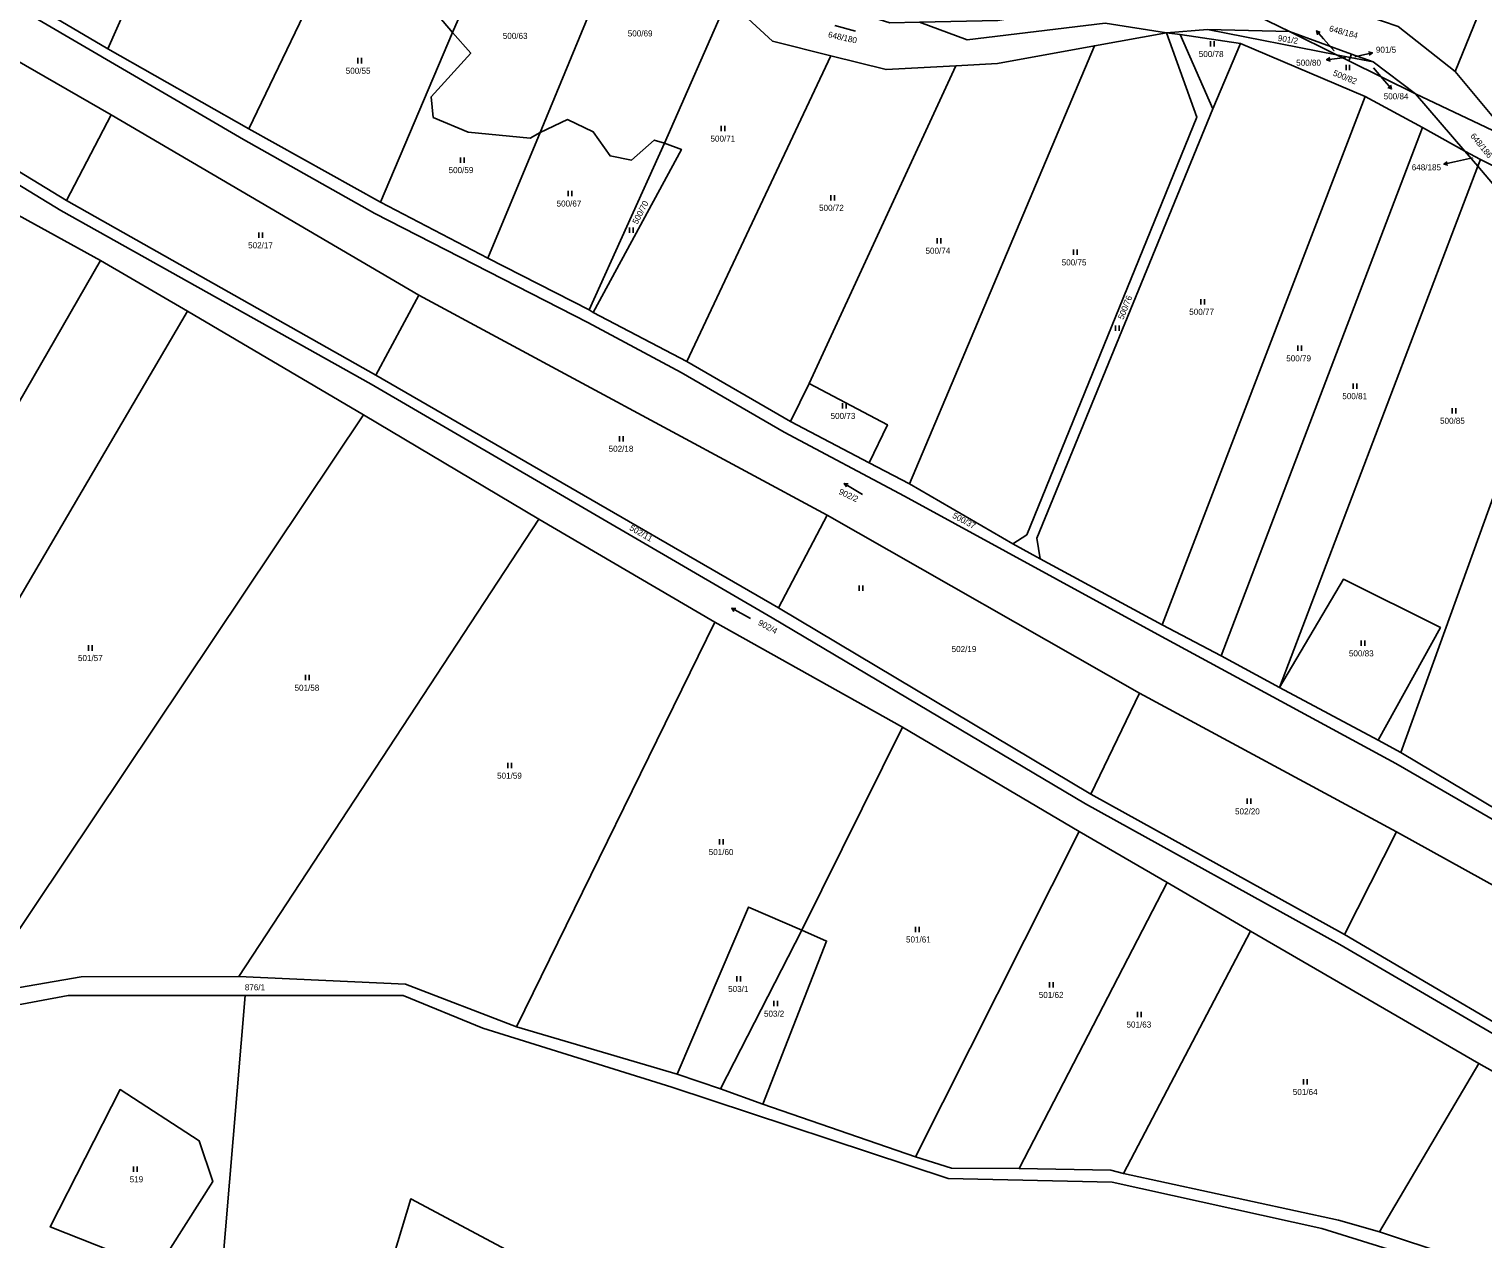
# Model space of a CAD drawing. Extents: x -654083 to -650132, y -1099819 to -1096699.
# Drawn here: x -651463.8 to -651055.5, y -1098945.7 to -1098606 of the extents above; entities that cross this region are included whole.
import ezdxf

# ---------------------------------------------------------------- set-up
doc = ezdxf.new("R2010")
doc.units = 0
for name, color, linetype in [('Obvody jako plochy', 7, 'Continuous'), ('Parcelní čísla', 7, 'Continuous'), ('Prvky pro prodl_ par_ č_', 7, 'Continuous'), ('Značky kultur', 7, 'Continuous')]:
    doc.layers.add(name, color=color, linetype=linetype)

msp = doc.modelspace()

# ---------------------------------------------------------------- linework, layer by layer
at = {"layer": 'Obvody jako plochy'}
for points in [[(-651063.28, -1098617.85), (-650992.27, -1098443.62), (-651020.25, -1098435.16), (-651088.04, -1098602.28), (-651079.27, -1098605.24)], [(-651003.38, -1098546.99), (-650965.66, -1098454.1), (-650992.27, -1098443.62), (-651063.28, -1098617.85), (-651047.34, -1098636.99), (-651041.11, -1098639.89)], [(-651454.84, -1098656.9), (-651367.65, -1098705.69), (-651255.05, -1098771.28), (-651167.08, -1098823.5), (-651095.7, -1098863.03), (-651026.53, -1098903.28), (-650920.69, -1098965.31), (-650919.42, -1098962.9), (-651025.16, -1098900.83), (-651094.31, -1098860.23), (-651165.63, -1098820.84), (-651253.31, -1098768.53), (-651366.33, -1098703.17), (-651453.26, -1098654.14), (-651533.95, -1098604.92), (-651656.86, -1098536.01), (-651727.45, -1098488.75), (-651724.94, -1098494.1), (-651658.3, -1098538.35), (-651535.47, -1098607.79)], [(-651421.47, -1098565.93), (-651441.62, -1098611.49), (-651493.57, -1098580.95), (-651487.96, -1098565.45), (-651484.16, -1098563.77), (-651469.58, -1098568.87), (-651465.42, -1098561.3), (-651459.25, -1098563.45), (-651455.59, -1098556.16), (-651451.67, -1098555.91), (-651448.17, -1098558.89), (-651436.53, -1098560.13)], [(-651378.31, -1098584.67), (-651402.01, -1098634.01), (-651441.62, -1098611.49), (-651421.47, -1098565.93), (-651416.15, -1098567.51), (-651409.43, -1098557.58), (-651379.54, -1098563.48), (-651382.87, -1098586.06)], [(-651358.17, -1098576.52), (-651353.62, -1098580.44), (-651342.23, -1098586.81), (-651337.11, -1098589.06), (-651344.85, -1098606.96), (-651349.04, -1098601.97), (-651352.21, -1098588.46), (-651365.97, -1098590.05), (-651374.97, -1098583.88), (-651378.31, -1098584.67), (-651365.38, -1098558.59), (-651356.99, -1098559.63)], [(-651144.32, -1098606.98), (-651161.55, -1098604.31), (-651200.28, -1098608.98), (-651213.68, -1098603.99), (-651222.06, -1098604.17), (-651232.76, -1098600.8), (-651247.53, -1098596.14), (-651261.66, -1098584.42), (-651285.2, -1098564.93), (-651298.69, -1098570.34), (-651294.76, -1098573.37), (-651267.62, -1098597.69), (-651254.98, -1098609.32), (-651238.61, -1098613.44), (-651223.08, -1098617.35), (-651203.46, -1098616.28), (-651191.83, -1098615.64), (-651164.56, -1098610.67)], [(-651298.69, -1098570.34), (-651294.76, -1098573.37), (-651320.23, -1098635.03), (-651323, -1098636.63), (-651340.48, -1098634.94), (-651350.26, -1098630.76), (-651350.85, -1098625.02), (-651339.7, -1098612.77), (-651344.85, -1098606.96), (-651337.11, -1098589.06), (-651320.53, -1098595), (-651318.9, -1098587.55), (-651332.29, -1098577.35), (-651330.66, -1098573.01), (-651312.14, -1098576.62)], [(-651267.62, -1098597.69), (-651285.31, -1098638.03), (-651288.17, -1098637.13), (-651294.58, -1098642.74), (-651300.6, -1098641.6), (-651305.34, -1098634.85), (-651312.56, -1098631.38), (-651320.23, -1098635.03), (-651294.76, -1098573.37)], [(-651533.95, -1098604.92), (-651453.26, -1098654.14), (-651440.71, -1098630.03), (-651522.93, -1098582.72)], [(-651365.05, -1098654.61), (-651402.01, -1098634.01), (-651378.31, -1098584.67), (-651374.97, -1098583.88), (-651365.97, -1098590.05), (-651352.21, -1098588.46), (-651349.04, -1098601.97), (-651344.85, -1098606.96)], [(-651086.29, -1098615.21), (-651074.38, -1098624.12), (-651047.34, -1098636.99), (-651063.28, -1098617.85), (-651079.27, -1098605.24), (-651088.04, -1098602.28), (-651107.21, -1098595.82), (-651118.44, -1098595.21), (-651137.16, -1098594.54), (-651144.61, -1098595.77), (-651144.24, -1098598.17), (-651124.82, -1098599.38), (-651109.83, -1098606.62), (-651092.38, -1098612.99)], [(-651267.62, -1098597.69), (-651254.98, -1098609.32), (-651238.61, -1098613.44), (-651279, -1098699.35), (-651305.31, -1098685.59), (-651280.55, -1098639.78), (-651285.31, -1098638.03)], [(-651144.24, -1098598.17), (-651124.82, -1098599.38), (-651109.83, -1098606.62), (-651132.85, -1098606.11), (-651144.32, -1098606.98), (-651161.55, -1098604.31), (-651200.28, -1098608.98), (-651213.68, -1098603.99), (-651191.66, -1098603.53), (-651155.38, -1098597.54), (-651147.66, -1098597.96)], [(-651350.26, -1098630.76), (-651340.48, -1098634.94), (-651323, -1098636.63), (-651320.23, -1098635.03), (-651334.92, -1098670.3), (-651365.05, -1098654.61), (-651344.85, -1098606.96), (-651339.7, -1098612.77), (-651350.85, -1098625.02)], [(-651183.56, -1098747.97), (-651135.83, -1098630.67), (-651144.32, -1098606.98), (-651164.56, -1098610.67), (-651216.52, -1098733.67), (-651187.46, -1098750.55)], [(-651140.53, -1098607.45), (-651131.35, -1098628.36), (-651180.77, -1098748.95), (-651179.8, -1098754.71), (-651187.46, -1098750.55), (-651183.56, -1098747.97), (-651135.83, -1098630.67), (-651144.32, -1098606.98)], [(-651060.54, -1098640.25), (-651072.45, -1098633.65), (-651088.54, -1098624.89), (-651123.55, -1098610.02), (-651140.53, -1098607.45), (-651144.32, -1098606.98), (-651132.85, -1098606.11), (-651096.6, -1098613.19), (-651093.16, -1098614.9), (-651074.38, -1098624.12)], [(-651140.53, -1098607.45), (-651123.55, -1098610.02), (-651131.35, -1098628.36)], [(-651096.6, -1098613.19), (-651132.85, -1098606.11), (-651109.83, -1098606.62)], [(-651092.38, -1098612.99), (-651092.77, -1098613.94), (-651096.6, -1098613.19), (-651109.83, -1098606.62)], [(-651164.56, -1098610.67), (-651216.52, -1098733.67), (-651227.79, -1098727.82), (-651222.69, -1098717.09), (-651244.68, -1098705.48), (-651203.46, -1098616.28), (-651191.83, -1098615.64)], [(-651123.55, -1098610.02), (-651131.35, -1098628.36), (-651180.77, -1098748.95), (-651179.8, -1098754.71), (-651145.52, -1098773.3), (-651088.54, -1098624.89)], [(-651223.08, -1098617.35), (-651203.46, -1098616.28), (-651244.68, -1098705.48), (-651249.89, -1098716.14), (-651279, -1098699.35), (-651238.61, -1098613.44)], [(-651092.77, -1098613.94), (-651093.16, -1098614.9), (-651096.6, -1098613.19)], [(-651086.29, -1098615.21), (-651092.77, -1098613.94), (-651093.16, -1098614.9), (-651074.38, -1098624.12)], [(-651086.29, -1098615.21), (-651092.77, -1098613.94), (-651092.38, -1098612.99)], [(-651056.15, -1098642.55), (-651060.54, -1098640.25), (-651074.38, -1098624.12), (-651047.34, -1098636.99), (-651036.18, -1098652.67)], [(-651072.45, -1098633.65), (-651088.54, -1098624.89), (-651145.52, -1098773.3), (-651128.97, -1098781.99)], [(-651354.32, -1098680.7), (-651366.33, -1098703.17), (-651453.26, -1098654.14), (-651440.71, -1098630.03)], [(-651300.6, -1098641.6), (-651294.58, -1098642.74), (-651288.17, -1098637.13), (-651285.31, -1098638.03), (-651306.5, -1098684.85), (-651334.92, -1098670.3), (-651320.23, -1098635.03), (-651312.56, -1098631.38), (-651305.34, -1098634.85)], [(-651056.89, -1098644.49), (-651112.64, -1098790.89), (-651128.97, -1098781.99), (-651072.45, -1098633.65), (-651060.54, -1098640.25)], [(-651280.55, -1098639.78), (-651285.31, -1098638.03), (-651306.5, -1098684.85), (-651305.31, -1098685.59)], [(-651056.15, -1098642.55), (-651056.89, -1098644.49), (-651060.54, -1098640.25)], [(-651052.75, -1098649.3), (-651056.89, -1098644.49), (-651112.64, -1098790.89), (-651094.67, -1098760.47), (-651067.39, -1098774.05), (-651084.91, -1098805.69), (-651078.51, -1098809.11), (-651031.87, -1098680.23)], [(-650975.84, -1098732.1), (-650938.96, -1098741.84), (-650958.03, -1098724.72), (-650970.31, -1098721.88), (-650991.5, -1098713.1), (-651003.01, -1098699.6), (-651011.95, -1098689.12), (-651026.94, -1098666.58), (-651036.18, -1098652.67), (-651056.15, -1098642.55), (-651056.89, -1098644.49), (-651052.75, -1098649.3), (-651031.87, -1098680.23), (-651016.73, -1098702.65), (-651007.13, -1098712.31), (-650998.21, -1098721.28)], [(-651620.11, -1098922.37), (-651601.42, -1098928.61), (-651591.88, -1098928.33), (-651517.31, -1098798.77), (-651443.74, -1098670.95), (-651468.65, -1098657.15), (-651544, -1098789.1)], [(-651545.85, -1098893.57), (-651540.07, -1098891), (-651479.44, -1098787.66), (-651419.27, -1098685.18), (-651443.74, -1098670.95), (-651517.31, -1098798.77), (-651591.88, -1098928.33), (-651578.84, -1098927.78)], [(-651366.33, -1098703.17), (-651253.31, -1098768.53), (-651239.65, -1098742.43), (-651354.32, -1098680.7)], [(-651016.73, -1098702.65), (-651031.87, -1098680.23), (-651078.51, -1098809.11), (-651046.34, -1098828.28), (-651007.13, -1098712.31)], [(-651478.94, -1098877.26), (-651369.81, -1098714.29), (-651419.27, -1098685.18), (-651479.44, -1098787.66), (-651540.07, -1098891), (-651519.92, -1098884.22)], [(-651222.69, -1098717.09), (-651227.79, -1098727.82), (-651249.89, -1098716.14), (-651244.68, -1098705.48)], [(-651404.88, -1098872.03), (-651320.58, -1098743.57), (-651369.81, -1098714.29), (-651478.94, -1098877.26), (-651449.17, -1098872.12)], [(-651151.94, -1098792.41), (-651165.63, -1098820.84), (-651253.31, -1098768.53), (-651239.65, -1098742.43)], [(-651320.58, -1098743.57), (-651271.18, -1098772.53), (-651326.86, -1098886.15), (-651358.02, -1098874.14), (-651404.88, -1098872.03)], [(-651112.64, -1098790.89), (-651094.67, -1098760.47), (-651067.39, -1098774.05), (-651084.91, -1098805.69)], [(-651246.76, -1098859.02), (-651218.49, -1098801.97), (-651271.18, -1098772.53), (-651326.86, -1098886.15), (-651281.75, -1098899.44), (-651261.75, -1098852.51)], [(-651079.7, -1098831.37), (-651094.31, -1098860.23), (-651165.63, -1098820.84), (-651151.94, -1098792.41)], [(-651214.84, -1098922.63), (-651168.89, -1098831.27), (-651218.49, -1098801.97), (-651246.76, -1098859.02), (-651239.81, -1098862.06), (-651257.67, -1098907.87)], [(-651185.7, -1098925.92), (-651144.15, -1098845.62), (-651168.89, -1098831.27), (-651214.84, -1098922.63), (-651204.7, -1098925.83)], [(-651007.86, -1098871.2), (-651025.16, -1098900.83), (-651094.31, -1098860.23), (-651079.7, -1098831.37)], [(-651156.38, -1098927.3), (-651120.77, -1098859.3), (-651144.15, -1098845.62), (-651185.7, -1098925.92), (-651159.96, -1098926.38)], [(-651269.6, -1098903.55), (-651246.76, -1098859.02), (-651261.75, -1098852.51), (-651281.75, -1098899.44)], [(-651246.76, -1098859.02), (-651239.81, -1098862.06), (-651257.67, -1098907.87), (-651269.6, -1098903.55)], [(-651084.56, -1098943.72), (-651056.64, -1098896.43), (-651120.77, -1098859.3), (-651156.38, -1098927.3), (-651096.03, -1098940.41)], [(-651562.04, -1098919.43), (-651544.18, -1098899.01), (-651522.54, -1098890.33), (-651452.79, -1098877.39), (-651403.08, -1098877.38), (-651410.88, -1098969.91), (-651414.46, -1098968.19), (-651420.96, -1098966.16), (-651452.49, -1098960.24), (-651458.72, -1098958.17), (-651510.21, -1098939.42)], [(-651011.82, -1098971.67), (-650988.09, -1098934.85), (-651056.64, -1098896.43), (-651084.56, -1098943.72), (-651024.43, -1098963.7)], [(-651415.99, -1098918.13), (-651412.14, -1098929.61), (-651427.78, -1098954.23), (-651457.87, -1098942.28), (-651438.21, -1098903.77)], [(-651438.21, -1098903.77), (-651415.99, -1098918.13), (-651412.14, -1098929.61), (-651427.78, -1098954.23), (-651457.87, -1098942.28)], [(-651372.63, -1098987.73), (-651356.57, -1098934.47), (-651253.84, -1098989.2), (-651272.85, -1099028.76), (-651281.82, -1099025.44), (-651284.74, -1099024.46), (-651334.09, -1099004.98), (-651342.85, -1099000.98), (-651349.24, -1098998.17)]]:
    msp.add_lwpolyline(points, close=True, dxfattribs=at)
for points in [[(-651007.86, -1098871.2), (-651079.7, -1098831.37), (-651151.94, -1098792.41), (-651239.65, -1098742.43), (-651354.32, -1098680.7), (-651440.71, -1098630.03), (-651522.93, -1098582.72)], [(-651495.03, -1098583.5), (-651403.53, -1098637.01), (-651366.68, -1098657.78), (-651306.82, -1098688.39), (-651280.65, -1098702.36), (-651251.68, -1098719.19), (-651217.94, -1098737.09), (-651146.74, -1098775.95), (-651079.9, -1098812.24), (-651047.37, -1098831)], [(-651495.03, -1098583.5), (-651403.53, -1098637.01), (-651366.68, -1098657.78), (-651306.82, -1098688.39), (-651280.65, -1098702.36), (-651251.68, -1098719.19), (-651217.94, -1098737.09), (-651146.74, -1098775.95), (-651079.9, -1098812.24), (-651047.37, -1098831)], [(-651046.34, -1098828.28), (-651078.51, -1098809.11), (-651084.91, -1098805.69), (-651112.64, -1098790.89), (-651128.97, -1098781.99), (-651145.52, -1098773.3), (-651179.8, -1098754.71), (-651187.46, -1098750.55), (-651216.52, -1098733.67), (-651227.79, -1098727.82), (-651249.89, -1098716.14), (-651279, -1098699.35), (-651305.31, -1098685.59), (-651306.5, -1098684.85), (-651334.92, -1098670.3), (-651365.05, -1098654.61), (-651402.01, -1098634.01), (-651441.62, -1098611.49), (-651493.57, -1098580.95)], [(-651535.47, -1098607.79), (-651454.84, -1098656.9), (-651367.65, -1098705.69), (-651255.05, -1098771.28), (-651167.08, -1098823.5), (-651095.7, -1098863.03), (-651026.53, -1098903.28)], [(-650988.09, -1098934.85), (-651056.64, -1098896.43), (-651120.77, -1098859.3), (-651144.15, -1098845.62), (-651168.89, -1098831.27), (-651218.49, -1098801.97), (-651271.18, -1098772.53), (-651320.58, -1098743.57), (-651369.81, -1098714.29), (-651419.27, -1098685.18), (-651443.74, -1098670.95), (-651468.65, -1098657.15)], [(-651024.43, -1098963.7), (-651084.56, -1098943.72), (-651096.03, -1098940.41), (-651156.38, -1098927.3), (-651159.96, -1098926.38), (-651185.7, -1098925.92), (-651204.7, -1098925.83), (-651214.84, -1098922.63), (-651257.67, -1098907.87), (-651269.6, -1098903.55), (-651281.75, -1098899.44), (-651326.86, -1098886.15), (-651358.02, -1098874.14), (-651404.88, -1098872.03), (-651449.17, -1098872.12), (-651478.94, -1098877.26)], [(-651522.54, -1098890.33), (-651452.79, -1098877.39), (-651403.08, -1098877.38), (-651358.7, -1098877.38), (-651336.31, -1098886.56), (-651283.28, -1098903.13), (-651205.68, -1098928.73), (-651159.6, -1098929.8), (-651100.74, -1098942.8), (-651077.85, -1098949.92)], [(-651077.85, -1098949.92), (-651100.74, -1098942.8), (-651159.6, -1098929.8), (-651205.68, -1098928.73), (-651283.28, -1098903.13), (-651336.31, -1098886.56), (-651358.7, -1098877.38), (-651403.08, -1098877.38), (-651410.88, -1098969.91)], [(-651372.63, -1098987.73), (-651356.57, -1098934.47), (-651253.84, -1098989.2)]]:
    msp.add_lwpolyline(points, dxfattribs=at)
at = {"layer": 'Prvky pro prodl_ par_ č_'}
for p, q in [((-651100.24, -1098608.73), (-651102.22, -1098606.48)), ((-651097.29, -1098612.08), (-651100.24, -1098608.73)), ((-651096.38, -1098614.23), (-651099.36, -1098614.57)), ((-651094.07, -1098613.96), (-651096.38, -1098614.23)), ((-651091.46, -1098613.78), (-651089.45, -1098613.31)), ((-651089.45, -1098613.31), (-651086.53, -1098612.62)), ((-651086.17, -1098616.88), (-651083.07, -1098620.5)), ((-651083.07, -1098620.5), (-651081.12, -1098622.78)), ((-651063.48, -1098643.28), (-651066.41, -1098643.94)), ((-651058.39, -1098642.13), (-651063.48, -1098643.28))]:
    msp.add_line(p, q, dxfattribs=at)
for points in [[(-651101.94, -1098607.56), (-651102.22, -1098606.48), (-651101.19, -1098606.9)], [(-651087.62, -1098612.37), (-651086.53, -1098612.62), (-651087.39, -1098613.34)], [(-651098.31, -1098614.96), (-651099.36, -1098614.57), (-651098.42, -1098613.96)], [(-651081.39, -1098621.69), (-651081.12, -1098622.78), (-651082.15, -1098622.34)], [(-651065.32, -1098644.21), (-651066.41, -1098643.94), (-651065.54, -1098643.23)]]:
    msp.add_lwpolyline(points, dxfattribs=at)
at = {"layer": 'Značky kultur'}
for p, q in [((-651231.63, -1098606.59), (-651237.43, -1098605.01)), ((-651131.97, -1098609.4), (-651131.97, -1098610.9)), ((-651130.95, -1098610.9), (-651130.95, -1098609.4)), ((-651371.43, -1098614.09), (-651371.43, -1098615.59)), ((-651370.41, -1098615.59), (-651370.41, -1098614.09)), ((-651093.92, -1098616.03), (-651093.92, -1098617.53)), ((-651092.9, -1098617.53), (-651092.9, -1098616.03)), ((-651269.43, -1098633.15), (-651269.43, -1098634.65)), ((-651268.41, -1098634.65), (-651268.41, -1098633.15)), ((-651342.59, -1098641.99), (-651342.59, -1098643.49)), ((-651341.57, -1098643.49), (-651341.57, -1098641.99)), ((-651312.34, -1098651.38), (-651312.34, -1098652.88)), ((-651311.32, -1098652.88), (-651311.32, -1098651.38)), ((-651238.56, -1098652.57), (-651238.56, -1098654.07)), ((-651237.54, -1098654.07), (-651237.54, -1098652.57)), ((-651399.24, -1098663.09), (-651399.24, -1098664.59)), ((-651398.21, -1098664.59), (-651398.21, -1098663.09)), ((-651295.11, -1098661.73), (-651295.11, -1098663.23)), ((-651294.08, -1098663.23), (-651294.08, -1098661.73)), ((-651208.74, -1098664.64), (-651208.74, -1098666.14)), ((-651207.71, -1098666.14), (-651207.71, -1098664.64)), ((-651170.46, -1098667.91), (-651170.46, -1098669.41)), ((-651169.44, -1098669.41), (-651169.44, -1098667.91)), ((-651134.72, -1098681.78), (-651134.72, -1098683.28)), ((-651133.7, -1098683.28), (-651133.7, -1098681.78)), ((-651158.65, -1098689.24), (-651158.65, -1098690.74)), ((-651157.62, -1098690.74), (-651157.62, -1098689.24)), ((-651107.43, -1098694.84), (-651107.43, -1098696.34)), ((-651106.41, -1098696.34), (-651106.41, -1098694.84)), ((-651091.94, -1098705.47), (-651091.94, -1098706.97)), ((-651090.92, -1098706.97), (-651090.92, -1098705.47)), ((-651235.32, -1098711.02), (-651235.32, -1098712.52)), ((-651234.3, -1098712.52), (-651234.3, -1098711.02)), ((-651064.14, -1098712.39), (-651064.14, -1098713.89)), ((-651063.11, -1098713.89), (-651063.11, -1098712.39)), ((-651297.94, -1098720.25), (-651297.94, -1098721.75)), ((-651296.92, -1098721.75), (-651296.92, -1098720.25)), ((-651229.69, -1098736.65), (-651234.83, -1098733.55)), ((-651230.65, -1098762.23), (-651230.65, -1098763.73)), ((-651229.62, -1098763.73), (-651229.62, -1098762.23)), ((-651261.18, -1098771.49), (-651266.44, -1098768.59)), ((-651447.05, -1098779.02), (-651447.05, -1098780.52)), ((-651446.03, -1098780.52), (-651446.03, -1098779.02)), ((-651089.7, -1098777.7), (-651089.7, -1098779.2)), ((-651088.68, -1098779.2), (-651088.68, -1098777.7)), ((-651386.16, -1098787.35), (-651386.16, -1098788.85)), ((-651385.14, -1098788.85), (-651385.14, -1098787.35)), ((-651329.3, -1098812.03), (-651329.3, -1098813.53)), ((-651328.28, -1098813.53), (-651328.28, -1098812.03)), ((-651121.65, -1098822.06), (-651121.65, -1098823.56)), ((-651120.62, -1098823.56), (-651120.62, -1098822.06)), ((-651269.89, -1098833.49), (-651269.89, -1098834.99)), ((-651268.86, -1098834.99), (-651268.86, -1098833.49)), ((-651214.82, -1098858.03), (-651214.82, -1098859.53)), ((-651213.8, -1098859.53), (-651213.8, -1098858.03)), ((-651264.99, -1098871.94), (-651264.99, -1098873.44)), ((-651263.96, -1098873.44), (-651263.96, -1098871.94)), ((-651177.16, -1098873.6), (-651177.16, -1098875.1)), ((-651176.14, -1098875.1), (-651176.14, -1098873.6)), ((-651254.56, -1098878.89), (-651254.56, -1098880.39)), ((-651253.54, -1098880.39), (-651253.54, -1098878.89)), ((-651152.51, -1098881.93), (-651152.51, -1098883.43)), ((-651151.48, -1098883.43), (-651151.48, -1098881.93)), ((-651105.88, -1098900.85), (-651105.88, -1098902.35)), ((-651104.85, -1098902.35), (-651104.85, -1098900.85)), ((-651434.46, -1098925.38), (-651434.46, -1098926.88)), ((-651433.44, -1098926.88), (-651433.44, -1098925.38))]:
    msp.add_line(p, q, dxfattribs=at)
for points in [[(-651234.23, -1098734.5), (-651234.83, -1098733.55), (-651233.72, -1098733.64)], [(-651265.8, -1098769.51), (-651266.44, -1098768.59), (-651265.32, -1098768.64)]]:
    msp.add_lwpolyline(points, dxfattribs=at)

# ---------------------------------------------------------------- texts
at = {"layer": 'Parcelní čísla'}
for s, p in [('500/63', (-651330.72, -1098608.73)), ('500/69', (-651295.62, -1098608.04)), ('500/78', (-651135.26, -1098613.83)), ('500/55', (-651374.82, -1098618.53)), ('500/71', (-651272.4, -1098637.58)), ('500/59', (-651345.94, -1098646.42)), ('500/67', (-651315.61, -1098655.81)), ('500/72', (-651241.9, -1098657.01)), ('502/17', (-651402.24, -1098667.53)), ('500/74', (-651212.01, -1098669.07)), ('500/75', (-651173.77, -1098672.34)), ('500/77', (-651137.95, -1098686.22)), ('500/79', (-651110.7, -1098699.28)), ('500/81', (-651094.96, -1098709.9)), ('500/73', (-651238.67, -1098715.45)), ('500/85', (-651067.51, -1098716.82)), ('502/18', (-651301, -1098724.68)), ('502/19', (-651204.68, -1098780.92)), ('501/57', (-651450.03, -1098783.45)), ('500/83', (-651093.11, -1098782.13)), ('501/58', (-651389.2, -1098791.79)), ('501/59', (-651332.32, -1098816.47)), ('502/20', (-651125.09, -1098826.5)), ('501/60', (-651272.89, -1098837.92)), ('501/61', (-651217.49, -1098862.47)), ('876/1', (-651403.16, -1098875.9)), ('503/1', (-651267.44, -1098876.37)), ('501/62', (-651180.2, -1098878.04)), ('503/2', (-651257.38, -1098883.32)), ('501/63', (-651155.57, -1098886.36)), ('501/64', (-651108.86, -1098905.29)), ('519', (-651435.5, -1098929.81))]:
    msp.add_text(s, height=1.7, dxfattribs=at).set_placement(p)
for s, height, rotation, p in [('648/180', 1.7, 347.427, (-651239.5, -1098608.25)), ('901/2', 1.7, 351.081, (-651113.16, -1098609.28)), ('648/184', 1.7, 345.051, (-651098.79, -1098606.55)), ('901/4', 0.1, 333.054, (-651097.29, -1098612.08)), ('500/80', 0.1, 339.336, (-651094.07, -1098613.96)), ('901/5', 0.1, 347.13, (-651091.46, -1098613.78)), ('500/82', 1.7, 337.941, (-651097.74, -1098618.95)), ('500/84', 0.1, 336.537, (-651086.17, -1098616.88)), ('648/186', 1.7, 309.447, (-651059.14, -1098636.04)), ('648/185', 0.1, 310.959, (-651058.39, -1098642.13)), ('500/70', 1.7, 62.595, (-651292.93, -1098660.92)), ('500/76', 1.7, 68.778, (-651156.45, -1098687.68)), ('902/2', 1.7, 335.034, (-651236.55, -1098736.46)), ('500/37', 1.7, 331.605, (-651204.62, -1098743.1)), ('502/11', 1.7, 330.219, (-651295.31, -1098746.55)), ('902/4', 1.7, 331.56, (-651259.19, -1098773.2))]:
    msp.add_text(s, height=height, rotation=rotation, dxfattribs=at).set_placement(p)
at = {"layer": 'Prvky pro prodl_ par_ č_'}
for s, p in [('901/5', (-651085.53, -1098612.62)), ('500/80', (-651107.91, -1098616.27)), ('500/84', (-651083.34, -1098625.69)), ('648/185', (-651075.46, -1098645.64))]:
    msp.add_text(s, height=1.7, dxfattribs=at).set_placement(p)

doc.saveas('drawing.dxf')
